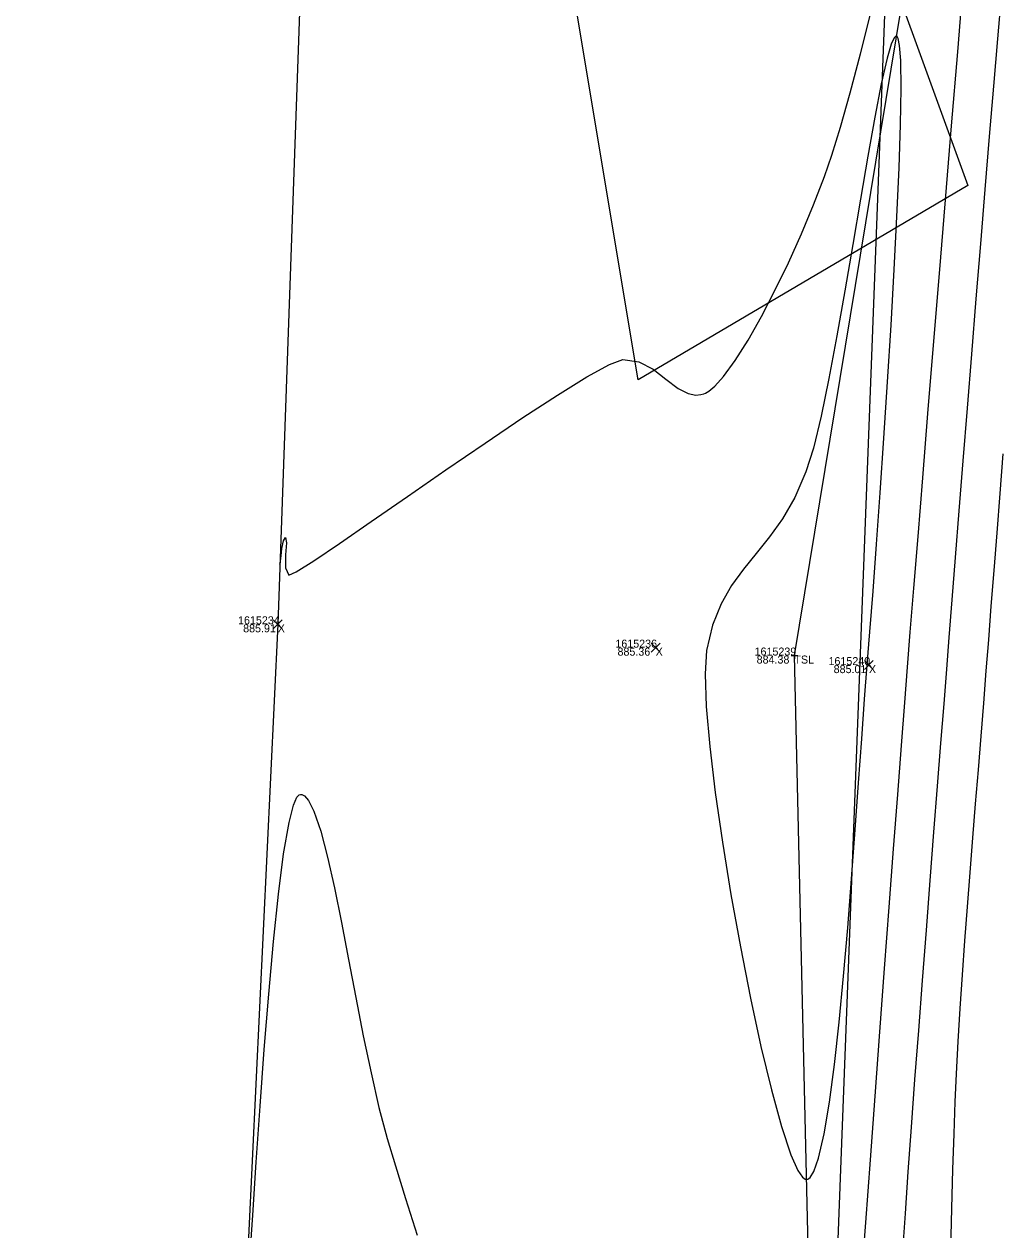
# Model space of a CAD drawing. Extents: x 1957117 to 1971063, y 701601 to 715861.
# Drawn here: x 1962653.6 to 1962696.4, y 702431.6 to 702484.4 of the extents above; entities that cross this region are included whole.
import ezdxf

# ---------------------------------------------------------------- set-up
doc = ezdxf.new("R2010")
doc.units = 0
for name, color, linetype in [('AP_X_Lights', 7, 'Continuous'), ('DT_X_Break_Line', 7, 'Continuous'), ('DT_X_Contour_Major', 7, 'Continuous'), ('DT_X_Contour_Minor', 7, 'Continuous'), ('DT_X_TIN_Hull', 7, 'Continuous'), ('PV_P_Drive', 7, 'Continuous'), ('PV_P_Shoulder', 7, 'Continuous'), ('RS_Raster1', 7, 'Continuous'), ('RW_X_Esmt_RR', 7, 'Continuous'), ('SC_Scratch1', 7, 'Continuous'), ('VG_X_Tree_Line_Rt', 7, 'Continuous')]:
    doc.layers.add(name, color=color, linetype=linetype)

msp = doc.modelspace()

# ---------------------------------------------------------------- linework, layer by layer
at = {"layer": 'AP_X_Lights'}
for p, q in [((1962664.537, 702457.917), (1962664.925, 702458.307)), ((1962664.537, 702458.307), (1962664.925, 702457.917)), ((1962681.059, 702456.896), (1962681.447, 702457.286)), ((1962681.059, 702457.286), (1962681.447, 702456.896)), ((1962690.384, 702456.133), (1962690.772, 702456.523)), ((1962690.384, 702456.523), (1962690.772, 702456.133))]:
    msp.add_line(p, q, dxfattribs=at)
at = {"layer": 'DT_X_Break_Line'}
msp.add_lwpolyline([(1962672.291, 702056.441), (1962678.402, 702106.354), (1962662.847, 702156.902), (1962653.64, 702207.97), (1962682.578, 702256.2), (1962687.088, 702305.912), (1962688.383, 702356.115), (1962688.326, 702413.221), (1962687.321, 702456.746), (1962695.78, 702508.037), (1962696.797, 702556.263), (1962699.455, 702605.505), (1962702.117, 702657.987), (1962703.272, 702699.736)], dxfattribs=at)
at = {"layer": 'DT_X_Contour_Major'}
msp.add_lwpolyline([(1962691.788, 702483.831), (1962691.753, 702483.824), (1962691.68, 702483.747), (1962691.558, 702483.48), (1962691.376, 702482.868), (1962691.121, 702481.744), (1962690.839, 702480.291), (1962690.535, 702478.585), (1962690.213, 702476.7), (1962689.877, 702474.71), (1962689.532, 702472.691), (1962689.183, 702470.718), (1962688.833, 702468.864), (1962688.488, 702467.205), (1962688.151, 702465.816), (1962687.828, 702464.771), (1962687.338, 702463.656), (1962686.797, 702462.728), (1962686.226, 702461.932), (1962685.65, 702461.215), (1962685.09, 702460.525), (1962684.571, 702459.808), (1962684.115, 702459.011), (1962683.745, 702458.081), (1962683.484, 702456.964), (1962683.419, 702455.946), (1962683.47, 702454.522), (1962683.622, 702452.768), (1962683.862, 702450.762), (1962684.174, 702448.581), (1962684.544, 702446.303), (1962684.958, 702444.005), (1962685.4, 702441.763), (1962685.857, 702439.656), (1962686.314, 702437.761), (1962686.756, 702436.154), (1962687.169, 702434.914), (1962687.469, 702434.237), (1962687.671, 702433.939), (1962687.793, 702433.85), (1962687.85, 702433.84), (1962687.905, 702433.852), (1962688.014, 702433.932), (1962688.173, 702434.19), (1962688.378, 702434.769), (1962688.621, 702435.83), (1962688.852, 702437.214), (1962689.07, 702438.864), (1962689.275, 702440.723), (1962689.469, 702442.735), (1962689.65, 702444.843), (1962689.82, 702446.991), (1962689.979, 702449.121), (1962690.126, 702451.177), (1962690.263, 702453.103), (1962690.39, 702454.842), (1962690.506, 702456.337), (1962690.622, 702457.788), (1962690.758, 702459.568), (1962690.909, 702461.615), (1962691.069, 702463.865), (1962691.232, 702466.254), (1962691.393, 702468.719), (1962691.545, 702471.196), (1962691.684, 702473.622), (1962691.803, 702475.933), (1962691.896, 702478.066), (1962691.959, 702479.957), (1962691.985, 702481.543), (1962691.969, 702482.759), (1962691.922, 702483.424), (1962691.865, 702483.721), (1962691.816, 702483.816)], close=True, dxfattribs=at)
msp.add_lwpolyline([(1962691.788, 702483.831), (1962691.753, 702483.824), (1962691.68, 702483.747), (1962691.558, 702483.48), (1962691.376, 702482.868), (1962691.121, 702481.744), (1962690.839, 702480.291), (1962690.535, 702478.585), (1962690.213, 702476.7), (1962689.877, 702474.71), (1962689.532, 702472.691), (1962689.183, 702470.718), (1962688.833, 702468.864), (1962688.488, 702467.205), (1962688.151, 702465.816), (1962687.828, 702464.771), (1962687.338, 702463.656), (1962686.797, 702462.728), (1962686.226, 702461.932), (1962685.65, 702461.215), (1962685.09, 702460.525), (1962684.571, 702459.808), (1962684.115, 702459.011), (1962683.745, 702458.081), (1962683.484, 702456.964), (1962683.419, 702455.946), (1962683.47, 702454.522), (1962683.622, 702452.768), (1962683.862, 702450.762), (1962684.174, 702448.581), (1962684.544, 702446.303), (1962684.958, 702444.005), (1962685.4, 702441.763), (1962685.857, 702439.656), (1962686.314, 702437.761), (1962686.756, 702436.154), (1962687.169, 702434.914), (1962687.469, 702434.237), (1962687.671, 702433.939), (1962687.793, 702433.85), (1962687.85, 702433.84), (1962687.905, 702433.852), (1962688.014, 702433.932), (1962688.173, 702434.19), (1962688.378, 702434.769), (1962688.621, 702435.83), (1962688.852, 702437.214), (1962689.07, 702438.864), (1962689.275, 702440.723), (1962689.469, 702442.735), (1962689.65, 702444.843), (1962689.82, 702446.991), (1962689.979, 702449.121), (1962690.126, 702451.177), (1962690.263, 702453.103), (1962690.39, 702454.842), (1962690.506, 702456.337), (1962690.622, 702457.788), (1962690.758, 702459.568), (1962690.909, 702461.615), (1962691.069, 702463.865), (1962691.232, 702466.254), (1962691.393, 702468.719), (1962691.545, 702471.196), (1962691.684, 702473.622), (1962691.803, 702475.933), (1962691.896, 702478.066), (1962691.959, 702479.957), (1962691.985, 702481.543), (1962691.969, 702482.759), (1962691.922, 702483.424), (1962691.865, 702483.721), (1962691.816, 702483.816)], close=True, dxfattribs=at)
at = {"layer": 'DT_X_Contour_Minor'}
for points in [[(1962690.246, 702429.319), (1962690.44, 702431.953), (1962690.643, 702434.692), (1962690.85, 702437.488), (1962691.06, 702440.294), (1962691.267, 702443.062), (1962691.468, 702445.747), (1962691.661, 702448.299), (1962691.841, 702450.672), (1962692.004, 702452.819), (1962692.148, 702454.692), (1962692.268, 702456.244), (1962692.389, 702457.765), (1962692.543, 702459.687), (1962692.726, 702461.956), (1962692.934, 702464.52), (1962693.162, 702467.326), (1962693.407, 702470.321), (1962693.664, 702473.452), (1962693.928, 702476.667), (1962694.195, 702479.912), (1962694.461, 702483.135), (1962694.722, 702486.283)], [(1962690.246, 702429.319), (1962690.44, 702431.953), (1962690.643, 702434.692), (1962690.85, 702437.488), (1962691.06, 702440.294), (1962691.267, 702443.062), (1962691.468, 702445.747), (1962691.661, 702448.299), (1962691.841, 702450.672), (1962692.004, 702452.819), (1962692.148, 702454.692), (1962692.268, 702456.244), (1962692.389, 702457.765), (1962692.543, 702459.687), (1962692.726, 702461.956), (1962692.934, 702464.52), (1962693.162, 702467.326), (1962693.407, 702470.321), (1962693.664, 702473.452), (1962693.928, 702476.667), (1962694.195, 702479.912), (1962694.461, 702483.135), (1962694.722, 702486.283)], [(1962692.063, 702430.717), (1962692.173, 702432.354), (1962692.3, 702434.171), (1962692.441, 702436.132), (1962692.594, 702438.204), (1962692.755, 702440.353), (1962692.922, 702442.543), (1962693.091, 702444.74), (1962693.259, 702446.911), (1962693.423, 702449.021), (1962693.581, 702451.034), (1962693.729, 702452.918), (1962693.864, 702454.638), (1962693.983, 702456.158), (1962694.092, 702457.541), (1962694.221, 702459.179), (1962694.368, 702461.035), (1962694.53, 702463.074), (1962694.705, 702465.259), (1962694.889, 702467.555), (1962695.08, 702469.926), (1962695.275, 702472.335), (1962695.471, 702474.748), (1962695.667, 702477.127), (1962695.858, 702479.436), (1962696.042, 702481.641), (1962696.216, 702483.704), (1962696.379, 702485.591)], [(1962692.063, 702430.717), (1962692.173, 702432.354), (1962692.3, 702434.171), (1962692.441, 702436.132), (1962692.594, 702438.204), (1962692.755, 702440.353), (1962692.922, 702442.543), (1962693.091, 702444.74), (1962693.259, 702446.911), (1962693.423, 702449.021), (1962693.581, 702451.034), (1962693.729, 702452.918), (1962693.864, 702454.638), (1962693.983, 702456.158), (1962694.092, 702457.541), (1962694.221, 702459.179), (1962694.368, 702461.035), (1962694.53, 702463.074), (1962694.705, 702465.259), (1962694.889, 702467.555), (1962695.08, 702469.926), (1962695.275, 702472.335), (1962695.471, 702474.748), (1962695.667, 702477.127), (1962695.858, 702479.436), (1962696.042, 702481.641), (1962696.216, 702483.704), (1962696.379, 702485.591)], [(1962664.824, 702460.736), (1962664.832, 702460.779), (1962664.849, 702460.892), (1962664.875, 702461.106), (1962664.916, 702461.423), (1962664.982, 702461.766), (1962665.073, 702461.909), (1962665.108, 702461.671), (1962665.069, 702461.144), (1962665.067, 702460.588), (1962665.211, 702460.261), (1962665.541, 702460.409), (1962666.307, 702460.892), (1962667.427, 702461.645), (1962668.818, 702462.601), (1962670.397, 702463.696), (1962672.084, 702464.862), (1962673.794, 702466.034), (1962675.446, 702467.147), (1962676.958, 702468.134), (1962678.247, 702468.93), (1962679.23, 702469.468), (1962679.826, 702469.684), (1962680.524, 702469.589), (1962681.141, 702469.262), (1962681.703, 702468.83), (1962682.241, 702468.421), (1962682.672, 702468.198), (1962683.005, 702468.133), (1962683.236, 702468.155), (1962683.354, 702468.188), (1962683.428, 702468.218), (1962683.584, 702468.31), (1962683.841, 702468.525), (1962684.219, 702468.943), (1962684.738, 702469.652), (1962685.297, 702470.538), (1962685.879, 702471.567), (1962686.472, 702472.705), (1962687.059, 702473.921), (1962687.626, 702475.179), (1962688.159, 702476.448), (1962688.644, 702477.693), (1962688.96, 702478.62), (1962689.333, 702479.848), (1962689.753, 702481.341), (1962690.21, 702483.059), (1962690.694, 702484.965)], [(1962664.824, 702460.736), (1962664.832, 702460.779), (1962664.849, 702460.892), (1962664.875, 702461.106), (1962664.916, 702461.423), (1962664.982, 702461.766), (1962665.073, 702461.909), (1962665.108, 702461.671), (1962665.069, 702461.144), (1962665.067, 702460.588), (1962665.211, 702460.261), (1962665.541, 702460.409), (1962666.307, 702460.892), (1962667.427, 702461.645), (1962668.818, 702462.601), (1962670.397, 702463.696), (1962672.084, 702464.862), (1962673.794, 702466.034), (1962675.446, 702467.147), (1962676.958, 702468.134), (1962678.247, 702468.93), (1962679.23, 702469.468), (1962679.826, 702469.684), (1962680.524, 702469.589), (1962681.141, 702469.262), (1962681.703, 702468.83), (1962682.241, 702468.421), (1962682.672, 702468.198), (1962683.005, 702468.133), (1962683.236, 702468.155), (1962683.354, 702468.188), (1962683.428, 702468.218), (1962683.584, 702468.31), (1962683.841, 702468.525), (1962684.219, 702468.943), (1962684.738, 702469.652), (1962685.297, 702470.538), (1962685.879, 702471.567), (1962686.472, 702472.705), (1962687.059, 702473.921), (1962687.626, 702475.179), (1962688.159, 702476.448), (1962688.644, 702477.693), (1962688.96, 702478.62), (1962689.333, 702479.848), (1962689.753, 702481.341), (1962690.21, 702483.059), (1962690.694, 702484.965)], [(1962696.438, 702465.571), (1962696.3, 702463.825), (1962696.166, 702462.118), (1962696.038, 702460.47), (1962695.917, 702458.899), (1962695.803, 702457.427), (1962695.697, 702456.073), (1962695.585, 702454.659), (1962695.469, 702453.216), (1962695.349, 702451.75), (1962695.229, 702450.266), (1962695.108, 702448.77), (1962694.989, 702447.268), (1962694.873, 702445.765), (1962694.761, 702444.269), (1962694.656, 702442.784), (1962694.559, 702441.316), (1962694.471, 702439.872), (1962694.394, 702438.456), (1962694.339, 702437.237), (1962694.288, 702435.833), (1962694.241, 702434.272), (1962694.195, 702432.578), (1962694.152, 702430.779)], [(1962696.438, 702465.571), (1962696.3, 702463.825), (1962696.166, 702462.118), (1962696.038, 702460.47), (1962695.917, 702458.899), (1962695.803, 702457.427), (1962695.697, 702456.073), (1962695.585, 702454.659), (1962695.469, 702453.216), (1962695.349, 702451.75), (1962695.229, 702450.266), (1962695.108, 702448.77), (1962694.989, 702447.268), (1962694.873, 702445.765), (1962694.761, 702444.269), (1962694.656, 702442.784), (1962694.559, 702441.316), (1962694.471, 702439.872), (1962694.394, 702438.456), (1962694.339, 702437.237), (1962694.288, 702435.833), (1962694.241, 702434.272), (1962694.195, 702432.578), (1962694.152, 702430.779)], [(1962663.496, 702430.171), (1962663.634, 702432.281), (1962663.787, 702434.6), (1962663.956, 702437.041), (1962664.139, 702439.519), (1962664.335, 702441.947), (1962664.542, 702444.241), (1962664.76, 702446.313), (1962664.989, 702448.078), (1962665.225, 702449.451), (1962665.42, 702450.209), (1962665.569, 702450.549), (1962665.67, 702450.658), (1962665.721, 702450.674), (1962665.78, 702450.67), (1962665.898, 702450.613), (1962666.075, 702450.41), (1962666.311, 702449.94), (1962666.608, 702449.07), (1962666.906, 702447.934), (1962667.208, 702446.586), (1962667.515, 702445.079), (1962667.827, 702443.464), (1962668.145, 702441.795), (1962668.472, 702440.126), (1962668.808, 702438.508), (1962669.155, 702436.994), (1962669.513, 702435.637), (1962669.872, 702434.432), (1962670.315, 702433.007), (1962670.826, 702431.403)], [(1962663.496, 702430.171), (1962663.634, 702432.281), (1962663.787, 702434.6), (1962663.956, 702437.041), (1962664.139, 702439.519), (1962664.335, 702441.947), (1962664.542, 702444.241), (1962664.76, 702446.313), (1962664.989, 702448.078), (1962665.225, 702449.451), (1962665.42, 702450.209), (1962665.569, 702450.549), (1962665.67, 702450.658), (1962665.721, 702450.674), (1962665.78, 702450.67), (1962665.898, 702450.613), (1962666.075, 702450.41), (1962666.311, 702449.94), (1962666.608, 702449.07), (1962666.906, 702447.934), (1962667.208, 702446.586), (1962667.515, 702445.079), (1962667.827, 702443.464), (1962668.145, 702441.795), (1962668.472, 702440.126), (1962668.808, 702438.508), (1962669.155, 702436.994), (1962669.513, 702435.637), (1962669.872, 702434.432), (1962670.315, 702433.007), (1962670.826, 702431.403)]]:
    msp.add_lwpolyline(points, dxfattribs=at)
at = {"layer": 'DT_X_TIN_Hull'}
msp.add_lwpolyline([(1962674.559, 702707.745), (1962673.32, 702658.081), (1962672.256, 702607.928), (1962668.525, 702557.8), (1962666.493, 702507.929), (1962664.731, 702458.112), (1962662.325, 702407.833), (1962660.262, 702358.239), (1962657.931, 702308.011), (1962655.854, 702258.355)], dxfattribs=at)
at = {"layer": 'PV_P_Drive'}
for p, q in [((1962687.175, 702456.746), (1962687.467, 702456.746)), ((1962687.321, 702456.892), (1962687.321, 702456.6)), ((1962687.321, 702456.746), (1962687.321, 702456.746))]:
    msp.add_line(p, q, dxfattribs=at)
at = {"layer": 'RW_X_Esmt_RR'}
msp.add_lwpolyline([(1962674.265, 702039.003), (1962716.391, 703142.573)], dxfattribs=at)
at = {"layer": 'VG_X_Tree_Line_Rt'}
msp.add_lwpolyline([(1962721.735, 702611.35), (1962721.735, 702611.35), (1962705.297, 702617.197), (1962700.781, 702604.223), (1962689.323, 702594.734), (1962688.714, 702576.961), (1962690.149, 702560.954), (1962713.542, 702563.222), (1962719.078, 702547.862), (1962711.672, 702534.39), (1962707.343, 702521.047), (1962699.664, 702515.683), (1962688.77, 702517.348), (1962687.493, 702503.385), (1962689.928, 702490.961), (1962694.909, 702477.301), (1962680.484, 702468.807), (1962676.811, 702490.839), (1962660.941, 702492.315)], dxfattribs=at)

# ---------------------------------------------------------------- texts
at = {"layer": 'PV_P_Shoulder'}
for s, p in [('885.91', (1962663.217, 702457.762)), ('885.36', (1962679.586, 702456.741)), ('884.38', (1962685.67, 702456.396)), ('885.01', (1962689.037, 702455.978))]:
    msp.add_text(s, height=0.35, dxfattribs=at).set_placement(p)
at = {"layer": 'RS_Raster1'}
for s, p in [('1615234', (1962662.995, 702458.112)), ('1615236', (1962679.492, 702457.091)), ('1615239', (1962685.58, 702456.746)), ('1615240', (1962688.812, 702456.328))]:
    msp.add_text(s, height=0.35, dxfattribs=at).set_placement(p)
at = {"layer": 'SC_Scratch1'}
for s, p in [('X', (1962664.731, 702457.762)), ('X', (1962681.253, 702456.741)), ('TSL', (1962687.321, 702456.396)), ('X', (1962690.578, 702455.978))]:
    msp.add_text(s, height=0.35, dxfattribs=at).set_placement(p)

doc.saveas('drawing.dxf')
